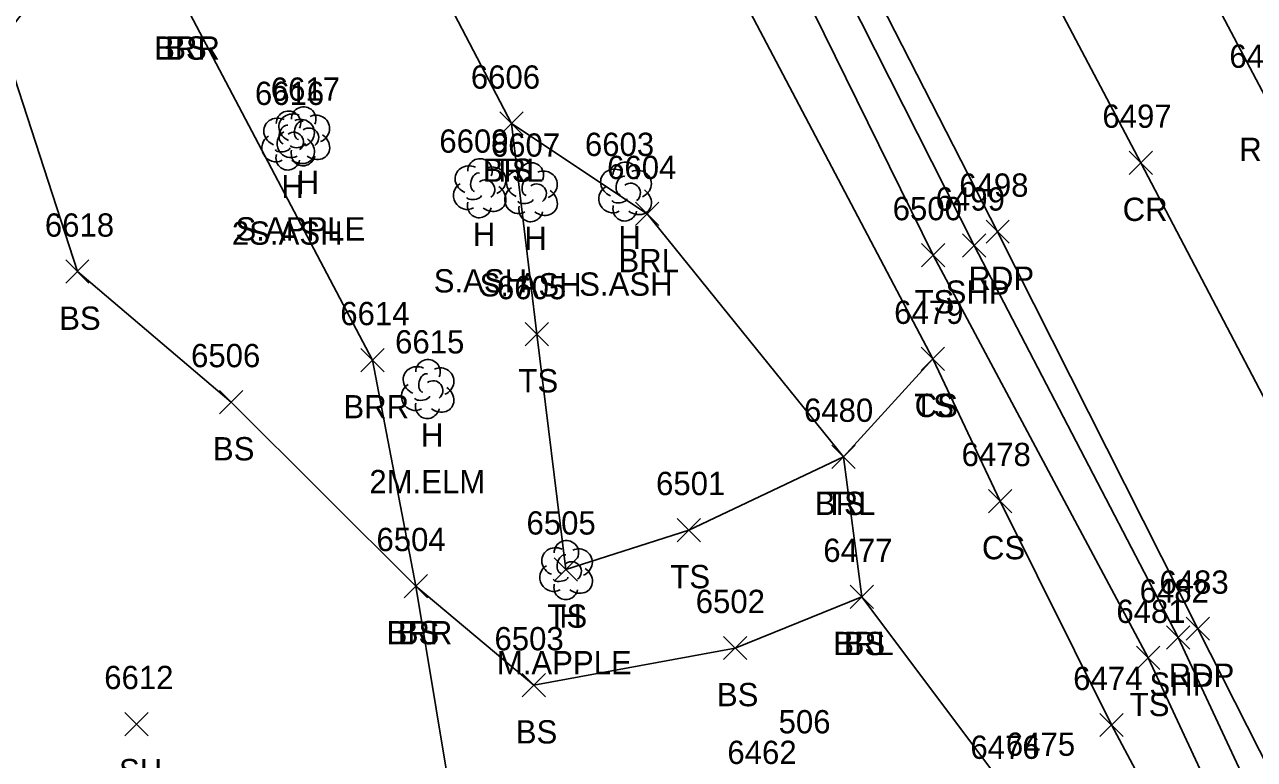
# Model space of a CAD drawing. Extents: x 1439173 to 1457902, y 641926 to 659889.
# Drawn here: x 1448822.7 to 1448928.4, y 643615.4 to 643678.5 of the extents above; entities that cross this region are included whole.
import ezdxf

# ---------------------------------------------------------------- set-up
doc = ezdxf.new("R2010")
doc.units = 0
for name, color, linetype in [('L_A', 7, 'Continuous'), ('L_C', 7, 'Continuous'), ('L_I', 7, 'Continuous'), ('L_TIC', 7, 'Continuous'), ('LABL', 7, 'Continuous'), ('LELB', 7, 'Continuous'), ('LTD', 7, 'Continuous'), ('M_I', 7, 'Continuous'), ('P_A', 7, 'Continuous'), ('P_I', 7, 'Continuous'), ('P_TIC', 7, 'Continuous'), ('PET', 7, 'Continuous'), ('PRC', 7, 'Continuous'), ('PSP', 7, 'Continuous')]:
    doc.layers.add(name, color=color, linetype=linetype)

msp = doc.modelspace()

# ---------------------------------------------------------------- linework, layer by layer
at = {"layer": 'L_TIC'}
for points in [[(1448863.56, 643669.04), (1448865.56, 643671.04)], [(1448865.56, 643669.04), (1448863.56, 643671.04)], [(1448863.56, 643669.04), (1448865.56, 643671.04)], [(1448865.56, 643669.04), (1448863.56, 643671.04)], [(1448875.21, 643661.28), (1448877.21, 643663.28)], [(1448877.21, 643661.28), (1448875.21, 643663.28)], [(1448899.78, 643657.74), (1448901.78, 643659.74)], [(1448901.78, 643657.74), (1448899.78, 643659.74)], [(1448826.26, 643656.33), (1448828.26, 643658.33)], [(1448828.26, 643656.33), (1448826.26, 643658.33)], [(1448865.75, 643650.96), (1448867.75, 643652.96)], [(1448867.75, 643650.96), (1448865.75, 643652.96)], [(1448851.63, 643648.73), (1448853.63, 643650.73)], [(1448853.63, 643648.73), (1448851.63, 643650.73)], [(1448899.76, 643648.84), (1448901.76, 643650.84)], [(1448901.76, 643648.84), (1448899.76, 643650.84)], [(1448899.76, 643648.84), (1448901.76, 643650.84)], [(1448901.76, 643648.84), (1448899.76, 643650.84)], [(1448839.47, 643645.12), (1448841.47, 643647.12)], [(1448841.47, 643645.12), (1448839.47, 643647.12)], [(1448892.09, 643640.43), (1448894.09, 643642.43)], [(1448894.09, 643640.43), (1448892.09, 643642.43)], [(1448892.09, 643640.43), (1448894.09, 643642.43)], [(1448894.09, 643640.43), (1448892.09, 643642.43)], [(1448905.54, 643636.63), (1448907.54, 643638.63)], [(1448907.54, 643636.63), (1448905.54, 643638.63)], [(1448878.8, 643634.14), (1448880.8, 643636.14)], [(1448880.8, 643634.14), (1448878.8, 643636.14)], [(1448868.24, 643630.75), (1448870.24, 643632.75)], [(1448870.24, 643630.75), (1448868.24, 643632.75)], [(1448855.35, 643629.33), (1448857.35, 643631.33)], [(1448857.35, 643629.33), (1448855.35, 643631.33)], [(1448855.35, 643629.33), (1448857.35, 643631.33)], [(1448857.35, 643629.33), (1448855.35, 643631.33)], [(1448893.66, 643628.4), (1448895.66, 643630.4)], [(1448895.66, 643628.4), (1448893.66, 643630.4)], [(1448893.66, 643628.4), (1448895.66, 643630.4)], [(1448895.66, 643628.4), (1448893.66, 643630.4)], [(1448882.77, 643624.01), (1448884.77, 643626.01)], [(1448884.77, 643624.01), (1448882.77, 643626.01)], [(1448918.27, 643623.16), (1448920.27, 643625.16)], [(1448920.27, 643623.16), (1448918.27, 643625.16)], [(1448865.49, 643620.81), (1448867.49, 643622.81)], [(1448867.49, 643620.81), (1448865.49, 643622.81)], [(1448831.35, 643617.48), (1448833.35, 643619.48)], [(1448833.35, 643617.48), (1448831.35, 643619.48)], [(1448915.12, 643617.4), (1448917.12, 643619.4)], [(1448917.12, 643617.4), (1448915.12, 643619.4)]]:
    msp.add_lwpolyline(points, dxfattribs=at)
at = {"layer": 'LABL'}
for points in [[(1448873.63, 643526.83), (1448861.8, 643539.89), (1448865.54, 643559.51), (1448866.62, 643564.49), (1448870.15, 643578.37), (1448861.57, 643598.71), (1448856.35, 643630.33), (1448852.63, 643649.73), (1448836.37, 643680.53), (1448847.58, 643687.34)], [(1448873.63, 643526.83), (1448888.26, 643523.8), (1448896.9, 643515.53), (1448904.97, 643503.03), (1448918.72, 643480.07), (1448931.25, 643488.01), (1448945.77, 643498.5), (1448954.67, 643515.64), (1448953.18, 643519.4), (1448950.69, 643524.77), (1448941.02, 643536.08), (1448931.04, 643573.57), (1448921.02, 643592.58), (1448912.31, 643600.43), (1448908.04, 643605.02), (1448907.35, 643612.49), (1448894.66, 643629.4), (1448893.09, 643641.43), (1448876.21, 643662.28), (1448864.56, 643670.04), (1448856.72, 643685.08), (1448847.58, 643687.34)]]:
    msp.add_lwpolyline(points, dxfattribs=at)
at = {"layer": 'LELB'}
for points in [[(1448940.79, 643577.93), (1448919.27, 643624.16), (1448900.78, 643658.74), (1448885.8, 643689.16), (1448877.75, 643703.58), (1448856.47, 643745.03), (1448837.55, 643780.25), (1448824.28, 643805.44), (1448810.73, 643829.91), (1448787.2, 643874.29), (1448782.43, 643882.71), (1448771.37, 643901.56), (1448759.4, 643927.61), (1448747.42, 643949.44), (1448734.25, 643972.55), (1448714.17, 644015.51), (1448690.32, 644058.37)], [(1448931.66, 643587.96), (1448924.07, 643603.5), (1448916.12, 643618.4), (1448906.54, 643637.63), (1448900.76, 643649.84), (1448881.42, 643686.55), (1448871.3, 643700.15), (1448853.2, 643742.83), (1448833.78, 643778.7), (1448820.49, 643802.12), (1448816.41, 643808.99), (1448806.7, 643827.13), (1448783.89, 643871.22), (1448779.41, 643878.86), (1448774.04, 643881.68)], [(1448894.66, 643629.4), (1448883.77, 643625.01), (1448866.49, 643621.81), (1448856.35, 643630.33), (1448840.47, 643646.12), (1448827.26, 643657.33), (1448820.79, 643677.26), (1448830.46, 643689.84), (1448847.21, 643705.04)], [(1448900.76, 643649.84), (1448893.09, 643641.43), (1448879.8, 643635.14), (1448869.24, 643631.75), (1448866.75, 643651.96), (1448864.56, 643670.04)]]:
    msp.add_lwpolyline(points, dxfattribs=at)
at = {"layer": 'LTD'}
for p, q in [((1448845.36, 643668.64), (1448845.36, 643668.64)), ((1448845.36, 643668.64), (1448845.36, 643668.64)), ((1448846.67, 643669), (1448846.67, 643669)), ((1448846.67, 643669), (1448846.67, 643669)), ((1448861.8, 643664.54), (1448861.8, 643664.54)), ((1448861.8, 643664.54), (1448861.8, 643664.54)), ((1448866.23, 643664.2), (1448866.23, 643664.2)), ((1448866.23, 643664.2), (1448866.23, 643664.2)), ((1448874.31, 643664.26), (1448874.31, 643664.26)), ((1448874.31, 643664.26), (1448874.31, 643664.26)), ((1448857.34, 643647.3), (1448857.34, 643647.3)), ((1448857.34, 643647.3), (1448857.34, 643647.3)), ((1448869.24, 643631.75), (1448869.24, 643631.75)), ((1448869.24, 643631.75), (1448869.24, 643631.75))]:
    msp.add_line(p, q, dxfattribs=at)
for centre in [(1448846.71, 643670.43), (1448845.4, 643670.07), (1448861.85, 643665.98), (1448866.27, 643665.63), (1448874.35, 643665.69), (1448857.39, 643648.73), (1448869.28, 643633.19)]:
    msp.add_arc(centre, 1.05, 335.5272, 180.9563, dxfattribs=at)
for centre, major_axis, ratio, start_param, end_param in [((1448844.57, 643669.31), (1.21, -0.51), 0.895232, 1.570796, 4.712389), ((1448845.87, 643669.67), (1.21, -0.51), 0.895232, 1.570796, 4.712389), ((1448846.46, 643669.46), (-0.208, -0.792), 0.645439, 3.141593, 6.283185), ((1448846.4, 643669.22), (-1.14, -0.48), 0.949671, 1.570796, 4.712389), ((1448847.71, 643669.58), (-1.14, -0.48), 0.949671, 1.570796, 4.712389), ((1448845.58, 643668.29), (0.58, -1.04), 0.959034, 3.141593, 6.283185), ((1448845.15, 643669.1), (-0.208, -0.792), 0.645439, 3.141593, 6.283185), ((1448845.86, 643668.47), (-0.5, 0.667), 0.989748, 3.141593, 6.283185), ((1448847.17, 643668.83), (-0.5, 0.667), 0.989748, 3.141593, 6.283185), ((1448844.27, 643667.93), (0.58, -1.04), 0.959034, 3.141593, 6.283185), ((1448846.21, 643668.25), (-0.625, -0.083), 0.423636, 0, 3.141593), ((1448846.36, 643667.81), (-1.09, 0.79), 0.841452, 1.570796, 4.712389), ((1448847.67, 643668.17), (-1.09, 0.79), 0.841452, 1.570796, 4.712389), ((1448845.36, 643667.14), (0.26, 1.06), 0.942809, 1.570796, 4.712389), ((1448844.9, 643667.89), (-0.625, -0.083), 0.423636, 0, 3.141593), ((1448846.67, 643667.5), (0.26, 1.06), 0.942809, 1.570796, 4.712389), ((1448861.01, 643665.21), (1.21, -0.51), 0.895232, 1.570796, 4.712389), ((1448862.85, 643665.13), (-1.14, -0.48), 0.949671, 1.570796, 4.712389), ((1448865.43, 643664.87), (1.21, -0.51), 0.895232, 1.570796, 4.712389), ((1448867.27, 643664.78), (-1.14, -0.48), 0.949671, 1.570796, 4.712389), ((1448873.51, 643664.93), (1.21, -0.51), 0.895232, 1.570796, 4.712389), ((1448875.35, 643664.84), (-1.14, -0.48), 0.949671, 1.570796, 4.712389), ((1448861.6, 643665), (-0.208, -0.792), 0.645439, 3.141593, 6.283185), ((1448862.3, 643664.38), (-0.5, 0.667), 0.989748, 3.141593, 6.283185), ((1448866.02, 643664.66), (-0.208, -0.792), 0.645439, 3.141593, 6.283185), ((1448866.73, 643664.03), (-0.5, 0.667), 0.989748, 3.141593, 6.283185), ((1448874.1, 643664.72), (-0.208, -0.792), 0.645439, 3.141593, 6.283185), ((1448874.81, 643664.09), (-0.5, 0.667), 0.989748, 3.141593, 6.283185), ((1448860.72, 643663.84), (0.58, -1.04), 0.959034, 3.141593, 6.283185), ((1448861.35, 643663.79), (-0.625, -0.083), 0.423636, 0, 3.141593), ((1448862.8, 643663.71), (-1.09, 0.79), 0.841452, 1.570796, 4.712389), ((1448865.14, 643663.49), (0.58, -1.04), 0.959034, 3.141593, 6.283185), ((1448867.23, 643663.37), (-1.09, 0.79), 0.841452, 1.570796, 4.712389), ((1448873.22, 643663.55), (0.58, -1.04), 0.959034, 3.141593, 6.283185), ((1448875.31, 643663.43), (-1.09, 0.79), 0.841452, 1.570796, 4.712389), ((1448861.81, 643663.04), (0.26, 1.06), 0.942809, 1.570796, 4.712389), ((1448866.23, 643662.7), (0.26, 1.06), 0.942809, 1.570796, 4.712389), ((1448865.77, 643663.45), (-0.625, -0.083), 0.423636, 0, 3.141593), ((1448874.31, 643662.76), (0.26, 1.06), 0.942809, 1.570796, 4.712389), ((1448873.85, 643663.51), (-0.625, -0.083), 0.423636, 0, 3.141593), ((1448856.55, 643647.97), (1.21, -0.51), 0.895232, 1.570796, 4.712389), ((1448858.39, 643647.88), (-1.14, -0.48), 0.949671, 1.570796, 4.712389), ((1448857.14, 643647.76), (-0.208, -0.792), 0.645439, 3.141593, 6.283185), ((1448857.84, 643647.13), (-0.5, 0.667), 0.989748, 3.141593, 6.283185), ((1448856.26, 643646.59), (0.58, -1.04), 0.959034, 3.141593, 6.283185), ((1448858.34, 643646.47), (-1.09, 0.79), 0.841452, 1.570796, 4.712389), ((1448857.35, 643645.8), (0.26, 1.06), 0.942809, 1.570796, 4.712389), ((1448856.89, 643646.55), (-0.625, -0.083), 0.423636, 0, 3.141593), ((1448868.45, 643632.42), (1.21, -0.51), 0.895232, 1.570796, 4.712389), ((1448870.28, 643632.34), (-1.14, -0.48), 0.949671, 1.570796, 4.712389), ((1448869.03, 643632.21), (-0.208, -0.792), 0.645439, 3.141593, 6.283185), ((1448869.74, 643631.59), (-0.5, 0.667), 0.989748, 3.141593, 6.283185), ((1448868.15, 643631.04), (0.58, -1.04), 0.959034, 3.141593, 6.283185), ((1448870.24, 643630.92), (-1.09, 0.79), 0.841452, 1.570796, 4.712389), ((1448869.24, 643630.25), (0.26, 1.06), 0.942809, 1.570796, 4.712389), ((1448868.78, 643631), (-0.625, -0.083), 0.423636, 0, 3.141593)]:
    msp.add_ellipse(centre, major_axis=major_axis, ratio=ratio, start_param=start_param, end_param=end_param, dxfattribs=at)
at = {"layer": 'P_TIC'}
for points in [[(1448917.64, 643665.68), (1448919.64, 643667.68)], [(1448919.64, 643665.68), (1448917.64, 643667.68)], [(1448905.33, 643659.76), (1448907.33, 643661.76)], [(1448907.33, 643659.76), (1448905.33, 643661.76)], [(1448903.32, 643658.57), (1448905.32, 643660.57)], [(1448905.32, 643658.57), (1448903.32, 643660.57)], [(1448920.84, 643624.91), (1448922.84, 643626.91)], [(1448922.84, 643624.91), (1448920.84, 643626.91)], [(1448922.53, 643625.67), (1448924.53, 643627.67)], [(1448924.53, 643625.67), (1448922.53, 643627.67)]]:
    msp.add_lwpolyline(points, dxfattribs=at)
at = {"layer": 'PET'}
for points in [[(1449162.58, 643198.27), (1449141.48, 643242.39), (1449121.69, 643284.02), (1449089.8, 643350.47), (1449063.61, 643404.76), (1449045.09, 643442.41), (1449024.86, 643484.45), (1449010.1, 643514.11), (1448990.81, 643553.04), (1448970.84, 643592.72), (1448947.22, 643637.96), (1448929.6, 643671.83), (1448913.03, 643703.21), (1448880.27, 643765.4), (1448860.14, 643803.65), (1448849.29, 643824.32), (1448831.93, 643857), (1448813.55, 643891.18), (1448792.86, 643930.51), (1448774.91, 643964.18), (1448756.71, 643999.72), (1448741.68, 644029.9), (1448721.66, 644072.11)], [(1449139.97, 643188.13), (1449117.6, 643232.77), (1449099.11, 643273.2), (1449066.34, 643340.97), (1449039.44, 643395.72), (1449020.72, 643432.95), (1449000.27, 643474.21), (1448984.45, 643505.7), (1448966.63, 643542.12), (1448946.78, 643580.8), (1448923.53, 643626.67), (1448906.33, 643660.76), (1448890.57, 643691.55), (1448882.77, 643706.14), (1448861.66, 643747.38), (1448842.89, 643782.5), (1448829.18, 643808.28), (1448815.05, 643835.06), (1448764.92, 643929.88), (1448739.21, 643978.47), (1448719.14, 644017.8), (1448697.57, 644061.64)]]:
    msp.add_lwpolyline(points, dxfattribs=at)
at = {"layer": 'PRC'}
msp.add_lwpolyline([(1449151.13, 643193.26), (1449129.92, 643237.18), (1449110.21, 643278.66), (1449077.82, 643346.33), (1449052.31, 643400.08), (1449033.57, 643437.64), (1449013.31, 643480.22), (1448998.17, 643509.98), (1448979.42, 643547.94), (1448960, 643587.03), (1448936.54, 643632.54), (1448918.64, 643666.68), (1448902.12, 643697.96), (1448893.71, 643713.68), (1448873.04, 643753.33), (1448854.51, 643788.55), (1448840.55, 643814.74), (1448825.9, 643842.48), (1448798.39, 643894.2), (1448777.05, 643935.06), (1448750.78, 643985.2), (1448731.14, 644023.28), (1448710.46, 644067.89)], dxfattribs=at)
at = {"layer": 'PSP'}
msp.add_lwpolyline([(1448943.46, 643579.59), (1448921.84, 643625.91), (1448904.32, 643659.57), (1448888.54, 643690.76), (1448881.08, 643705.57), (1448860.26, 643746.81), (1448841.85, 643781.75), (1448827.91, 643807.72), (1448814.1, 643834.43), (1448788.68, 643883.02), (1448774.83, 643907.87), (1448763.64, 643929.45), (1448738.41, 643977.89), (1448718.77, 644017.47), (1448697.57, 644061.64)], dxfattribs=at)

# ---------------------------------------------------------------- texts
at = {"layer": 'L_A'}
for s, p in [('BRR', (1448833.86, 643675.53)), ('BS', (1448834.81, 643675.53)), ('BRL', (1448862.1, 643665.04)), ('TS', (1448862.96, 643665.04)), ('H', (1448846.1, 643664)), ('H', (1448844.79, 643663.64)), ('H', (1448861.24, 643659.54)), ('H', (1448865.66, 643659.2)), ('H', (1448873.74, 643659.26)), ('BRL', (1448873.75, 643657.28)), ('TS', (1448899.19, 643653.74)), ('BS', (1448825.7, 643652.33)), ('TS', (1448865.16, 643646.96)), ('BRR', (1448850.12, 643644.73)), ('TS', (1448899.16, 643644.84)), ('CS', (1448899.2, 643644.84)), ('H', (1448856.78, 643642.3)), ('BS', (1448838.91, 643641.12)), ('BRL', (1448890.63, 643636.43)), ('TS', (1448891.5, 643636.43)), ('CS', (1448904.98, 643632.63)), ('TS', (1448878.21, 643630.14)), ('TS', (1448867.65, 643626.75)), ('H', (1448868.67, 643626.75)), ('BRR', (1448853.83, 643625.33)), ('BS', (1448854.79, 643625.33)), ('BRL', (1448892.2, 643624.4)), ('BS', (1448893.1, 643624.4)), ('BS', (1448882.21, 643620.01)), ('TS', (1448917.68, 643619.16)), ('BS', (1448864.93, 643616.81)), ('SH', (1448830.84, 643613.48))]:
    msp.add_text(s, height=2, dxfattribs=at).set_placement(p)
at = {"layer": 'L_C'}
for s, p in [('S.APPLE', (1448840.85, 643660)), ('2S.ASH', (1448840.54, 643659.64)), ('S.ASH', (1448857.88, 643655.54)), ('S. ASH', (1448861.82, 643655.2)), ('S.ASH', (1448870.38, 643655.26)), ('2M.ELM', (1448852.35, 643638.3)), ('M.APPLE', (1448863.3, 643622.75))]:
    msp.add_text(s, height=2, dxfattribs=at).set_placement(p)
at = {"layer": 'L_I'}
for s, p in [('6606', (1448861.07, 643673.04)), ('6606', (1448861.07, 643673.04)), ('6616', (1448842.52, 643671.64)), ('6617', (1448843.88, 643672)), ('6609', (1448858.36, 643667.54)), ('6607', (1448862.79, 643667.2)), ('6603', (1448870.87, 643667.26)), ('6604', (1448872.78, 643665.28)), ('6500', (1448897.31, 643661.74)), ('6618', (1448824.47, 643660.33)), ('6605', (1448863.31, 643654.96)), ('6614', (1448849.85, 643652.73)), ('6479', (1448897.44, 643652.84)), ('6479', (1448897.44, 643652.84)), ('6615', (1448854.56, 643650.3)), ('6506', (1448837.03, 643649.12)), ('6480', (1448889.69, 643644.43)), ('6480', (1448889.69, 643644.43)), ('6478', (1448903.23, 643640.63)), ('6501', (1448876.98, 643638.14)), ('6505', (1448865.85, 643634.75)), ('6505', (1448865.85, 643634.75)), ('6504', (1448852.96, 643633.33)), ('6504', (1448852.96, 643633.33)), ('6477', (1448891.35, 643632.4)), ('6477', (1448891.35, 643632.4)), ('6502', (1448880.39, 643628.01)), ('6481', (1448916.53, 643627.16)), ('6503', (1448863.1, 643624.81)), ('6612', (1448829.57, 643621.48)), ('6474', (1448912.82, 643621.4)), ('6476', (1448903.99, 643615.49)), ('6476', (1448903.99, 643615.49)), ('6476', (1448903.99, 643615.49)), ('6475', (1448907.04, 643615.75)), ('6462', (1448883.11, 643615.05))]:
    msp.add_text(s, height=2, dxfattribs=at).set_placement(p)
at = {"layer": 'M_I'}
msp.add_text('506', height=2, dxfattribs=at).set_placement((1448887.51, 643617.68))
at = {"layer": 'P_A'}
for s, p in [('RDP', (1448927.09, 643666.83)), ('CR', (1448917.07, 643661.68)), ('RDP', (1448903.82, 643655.76)), ('SHP', (1448901.86, 643654.57)), ('SHP', (1448919.37, 643620.91)), ('RDP', (1448921.02, 643621.67))]:
    msp.add_text(s, height=2, dxfattribs=at).set_placement(p)
at = {"layer": 'P_I'}
for s, p in [('6496', (1448926.24, 643674.83)), ('6497', (1448915.33, 643669.68)), ('6498', (1448903.03, 643663.76)), ('6499', (1448901.01, 643662.57)), ('6483', (1448920.23, 643629.67)), ('6482', (1448918.53, 643628.91))]:
    msp.add_text(s, height=2, dxfattribs=at).set_placement(p)

doc.saveas('drawing.dxf')
